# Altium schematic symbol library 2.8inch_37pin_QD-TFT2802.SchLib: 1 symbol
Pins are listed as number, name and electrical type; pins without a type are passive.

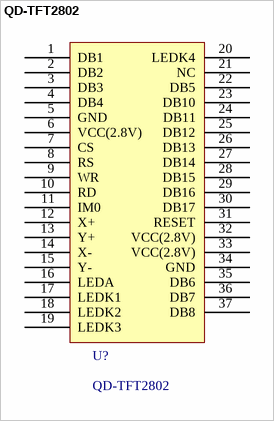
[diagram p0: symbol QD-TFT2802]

## QD-TFT2802
designator U?
2.8 TFT
pins: 1 DB1, 2 DB2, 3 DB3, 4 DB4, 5 GND, 6 VCC(2.8V), 7 CS, 8 RS, 9 WR, 10 RD, 11 IM0, 12 X+, 13 Y+, 14 X-, 15 Y-, 16 LEDA, 17 LEDK1, 18 LEDK2, 19 LEDK3, 20 LEDK4, 21 NC, 22 DB5, 23 DB10, 24 DB11, 25 DB12, 26 DB13, 27 DB14, 28 DB15, 29 DB16, 30 DB17, 31 RESET, 32 VCC(2.8V), 33 VCC(2.8V), 34 GND, 35 DB6, 36 DB7, 37 DB8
